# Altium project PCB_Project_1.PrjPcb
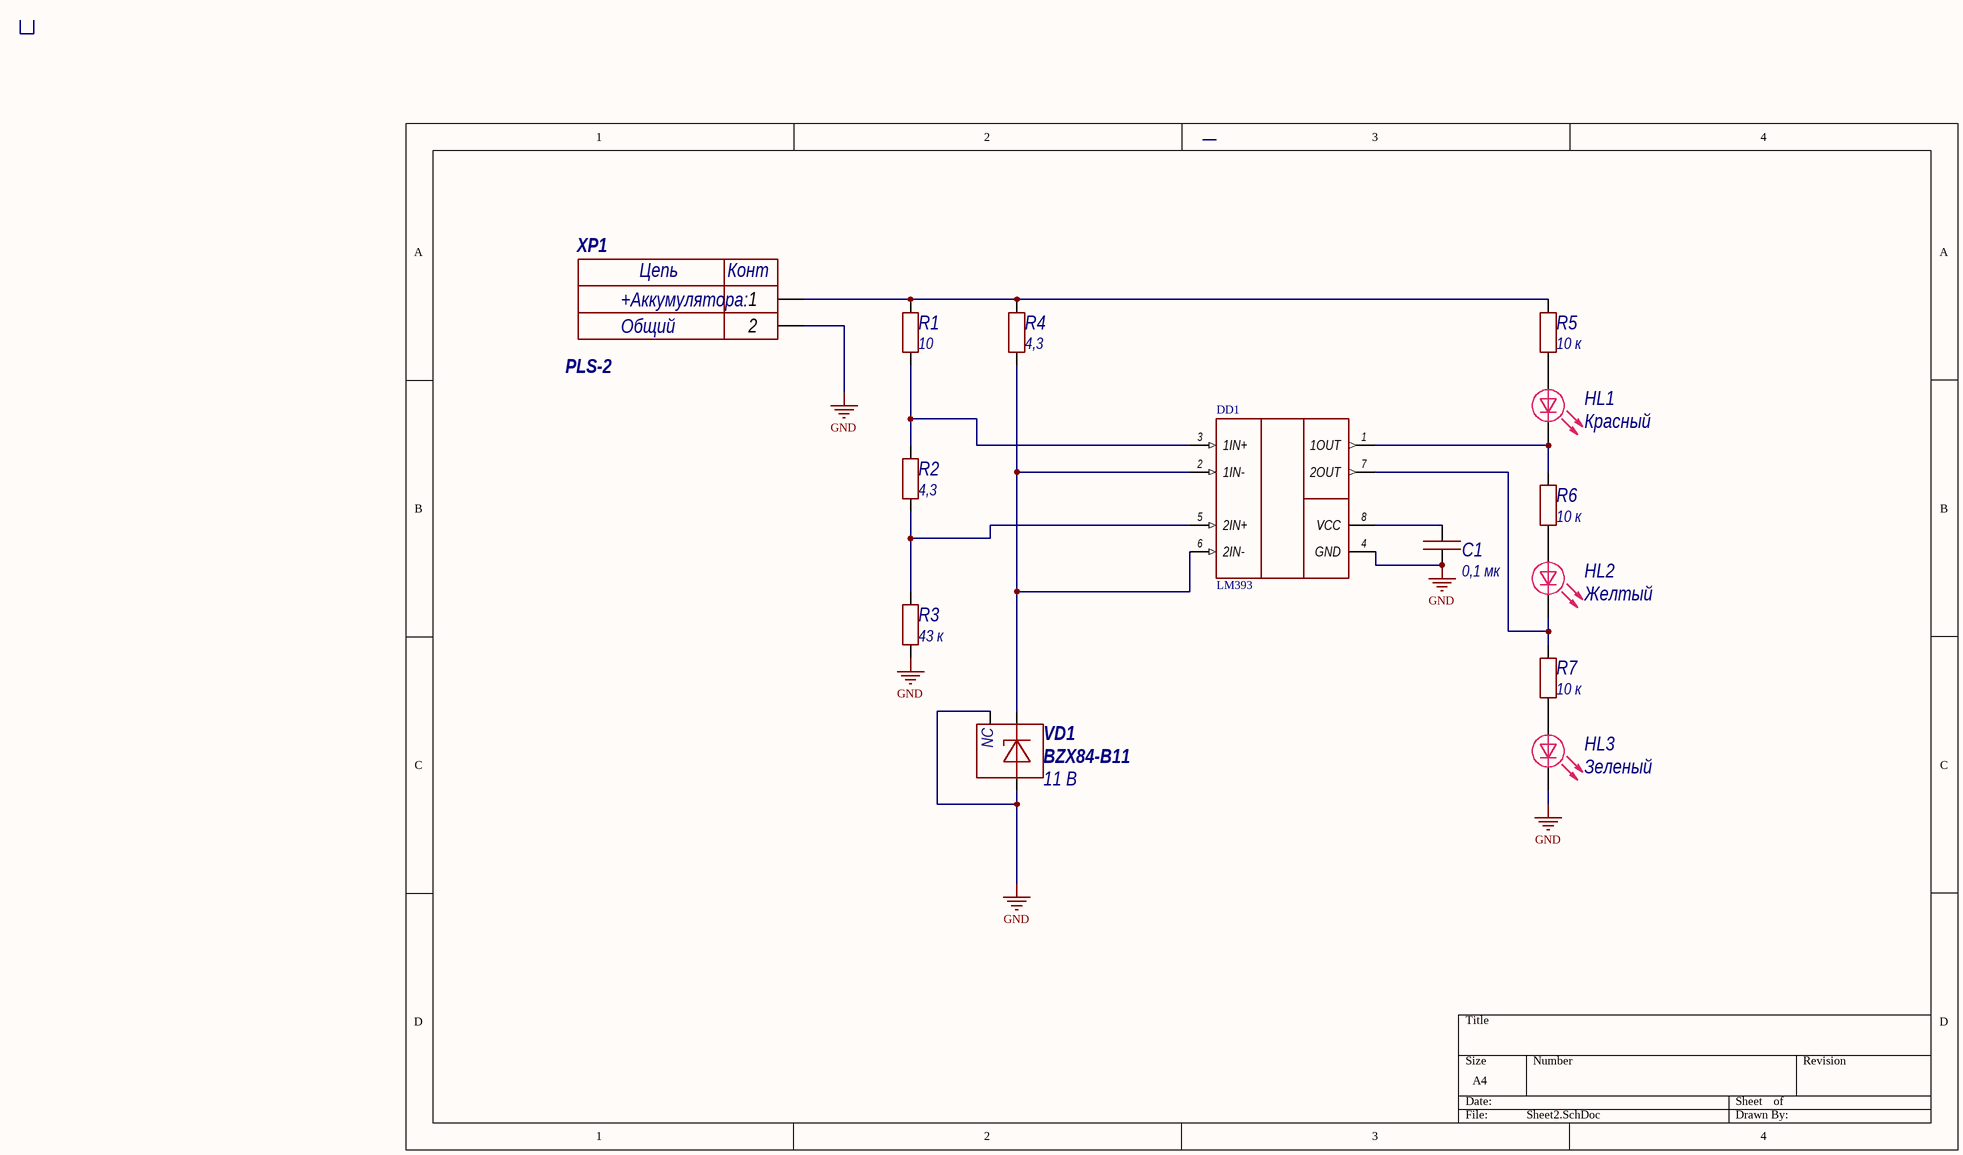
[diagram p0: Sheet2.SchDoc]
1 sheet, 14 parts. Net scope: global (net labels, ports and power ports of the same name join across sheets).
Board files: PCB1.PcbDoc, PCB2.PcbDoc

## Sheet Sheet2.SchDoc
size A4; SheetNumber: 1; SheetTotal: 1

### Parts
C1  value 0,1 мк  [0603C]  (hidden comment: Capacitor)
DD1  LM393  [SOIC-8]
HL1  Color: Красный  [0805D]  (hidden comment: LED)
HL2  Color: Желтый  [0805D]  (hidden comment: LED)
HL3  Color: Зеленый  [0805D]  (hidden comment: LED)
R1  value 10  [0603R]  (hidden comment: Resistor)
R2  value 4,3  [0603R]  (hidden comment: Resistor)
R3  value 43 к  [0603R]  (hidden comment: Resistor)
R4  value 4,3  [0603R]  (hidden comment: Resistor)
R5  value 10 к  [0603R]  (hidden comment: Resistor)
R6  value 10 к  [0603R]  (hidden comment: Resistor)
R7  value 10 к  [0603R]  (hidden comment: Resistor)
VD1  BZX84-B11  value 11 В  [SOT23-3]
XP1  PLS-2  [PLS2]

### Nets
GND: C1.1 DD1.4(GND) HL3.2 R3.1 VD1.1 VD1.2 XP1.2
NetC1_2: C1.2 DD1.8(VCC)
NetDD1_1: DD1.1(1OUT) HL1.2 R6.2
NetDD1_2: DD1.2(1IN-) DD1.6(2IN-) R4.1 VD1.3
NetDD1_3: DD1.3(1IN+) R1.1 R2.2
NetDD1_5: DD1.5(2IN+) R2.1 R3.2
NetDD1_7: DD1.7(2OUT) HL2.2 R7.2
NetHL1_1: HL1.1 R5.1
NetHL2_1: HL2.1 R6.1
NetHL3_1: HL3.1 R7.1
NetR1_2: R1.2 R4.2 R5.2 XP1.1

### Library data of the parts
C1 = Capacitor_0,1u_10_50V_X7R_0603C: Конденсатор 0603C ёмкостью 0,1 мк 10%, 50 В, X7R; Library Path2: Schematic\Capacitor.SchLib; Voltage (V): 50; Capacity (nF): 100
DD1 = LM393: Двойной маломощный компаратор напряжения; MF: Texas Instruments; MP: LM393D
HL1-HL3 = LED: Светодиод
R1 = Resistor_10_1_0603: Резистор номиналом 10 Ом 1%
R2 R4 = Resistor_4.3_1_0603: Резистор номиналом 4,3 Ом 1%
R3 = Resistor_43k_1_0603: Резистор номиналом 43 кОм 1%
R5-R7 = Resistor_10k_1_0603: Резистор номиналом 10 кОм 1%
VD1 = BZX84-B11: Стабилитрон на 11 В, рассеиваемая мощность 0.25 Вт; Voltage nominal (V): 11; Current nominal (mA): 5; Power (W): 0.25; Accuracy: 0,02
XP1 = PLS-2: Гребенка 2 пина; System: Connector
